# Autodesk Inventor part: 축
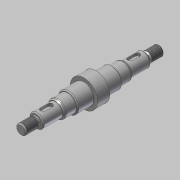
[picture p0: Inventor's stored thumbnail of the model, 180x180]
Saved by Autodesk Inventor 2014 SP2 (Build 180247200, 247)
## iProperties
Created: 2019-09
Part Number: 축
Material: 강철, 연강
Document SubType Name: Modeling
Designer: mduedu
Density: 7.86 g/cm^3
Mass: 210.278 g
Surface Area: 69.4769 cm^2
Volume: 26.7529 cm^3
Appearance: 강철
Author: mduedu
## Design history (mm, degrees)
sketch "스케치1"
  geometry: L1 (0, 0)-(15, 0); L2 (15, 0)-(15, 5); L3 (15, 5)-(0, 5); L4 (0, 5)-(0, 0); L5 (15, 0)-(34, 0); L6 (34, 0)-(34, 7); L7 (34, 7)-(15, 7); L8 (15, 7)-(15, 0); L9 (34, 0)-(46, 0); L10 (46, 0)-(46, 8.5); L11 (46, 8.5)-(34, 8.5); L12 (34, 8.5)-(34, 0); L13 (46, 0)-(62, 0); L14 (62, 10)-(46, 10); L15 (46, 10)-(46, 0); L16 (62, 10)-(62, 0); L17 (62, 0)-(68, 0); L18 (68, 0)-(68, 13.5); L19 (68, 13.5)-(62, 13.5); L20 (62, 13.5)-(62, 0)
  constraints: 40 end point, 10 parallel, 5 horizontal, 4 perpendicular, 1 vertical
  dimensions: "d2" = 15 distance of L2.end L3.end; "d3" = 19 distance of L6.end L7.end; "d8" = 16 distance of L14.start L14.end; "d9" = 10 diameter of L3 L1; "d10" = 14 diameter of L7 L5; "d11" = 17 diameter of L11 L9; "d12" = 20 diameter of L14 L13; "d73" = 12 distance of L10.end L11.end (derived); "d74" = 27 diameter of L19 L17; "d75" = 6 distance of L18.end L19.end; "d76" = 68 distance between parallel lines of L4 L18
revolve "회전1" sketch "스케치1" stored, may be unused: angle "d17" = 90 deg
revolve "회전2" stored, may be unused: angle "d22" = 90 deg
fillet "모깎기1" dims "d23" = 0.6
feature "스레드1" dims "d24" = 10, "d25" = 0
chamfer "모따기1" distance "d26" = 1; stored, may be unused: second distance "d27" = 2, angle "d28" = 45 deg
chamfer "모따기2" distance "d29" = 1; stored, may be unused: second distance "d30" = 2, angle "d31" = 45 deg
chamfer "모따기3" distance "d32" = 1.819; stored, may be unused: second distance "d33" = 2, angle "d34" = 30 deg
fillet "모깎기2" dims "d35" = 2
chamfer "모따기4" distance "d36" = 1; stored, may be unused: second distance "d37" = 2, angle "d38" = 30 deg
fillet "모깎기3" dims "d39" = 0.3
node "작업 평면1"
sketch "스케치3" dims "d51" = 12
  geometry: L1 (3, -2.5)-(-4, -2.5); L2 (-4, -2.5)-(-4, 2.5); L3 (-4, 2.5)-(3, 2.5); L4 (3, 2.5)-(3, -2.5); L5 (-9.5, 7.45)-(-9.5, -7.45) reference; 3 further points
  constraints: 8 end point, 2 midpoint, 2 parallel, 2 vertical alignment, 1 horizontal, 1 horizontal alignment, 1 perpendicular, 4 other
  dimensions: "d50" = 3 dimension on L5; "d52" = 5 distance between parallel lines of L3 L1
extrude "돌출1" cut sketch "스케치3" distance "d53" = 3; taper "d54" = 0 deg
node "솔리드1"
mirror "대칭1"
sketch "스케치2"
  geometry: L1 (0, -5)-(0, 5) reference; L2 (0, 5)-(15, 5) reference; L3 (15, 5)-(15, 7) reference; L4 (15, 7)-(34, 7) reference; L5 (34, 7)-(34, 8.5) reference; L6 (34, 8.5)-(46, 8.5) reference; L7 (46, 8.5)-(46, 10) reference; L8 (46, 10)-(62, 10) reference; L9 (62, -10)-(46, -10) reference; L10 (46, -10)-(46, -8.5) reference; L11 (46, -8.5)-(34, -8.5) reference; L12 (34, -8.5)-(34, -7) reference; L13 (34, -7)-(15, -7) reference; L14 (15, -7)-(15, -5) reference; L15 (15, -5)-(0, -5) reference; L16 (0, 0)-(74, 0); L17 (15, 5)-(12.014, 5); L18 (13.4, 4.2)-(15, 4.2); L19 (15, 4.2)-(15, 5); L20 (12.014, 5)-(13.4, 4.2); L21 (62, 10)-(62, 13.5) reference; L22 (62, 13.5)-(68, 13.5) reference; L23 (68, 13.5)-(68, -13.5) reference; L24 (68, -13.5)-(62, -13.5) reference; L25 (62, -13.5)-(62, -10) reference
  constraints: 10 end point, 1 horizontal, 1 parallel, 1 vertical
  dimensions: "d18" = 30 deg angle of L2 L20; "d19" = 8.4 diameter of L18 L16; "d21" = 2.986 distance from line of L17.end L19
node "절단 모서리 투영1"
